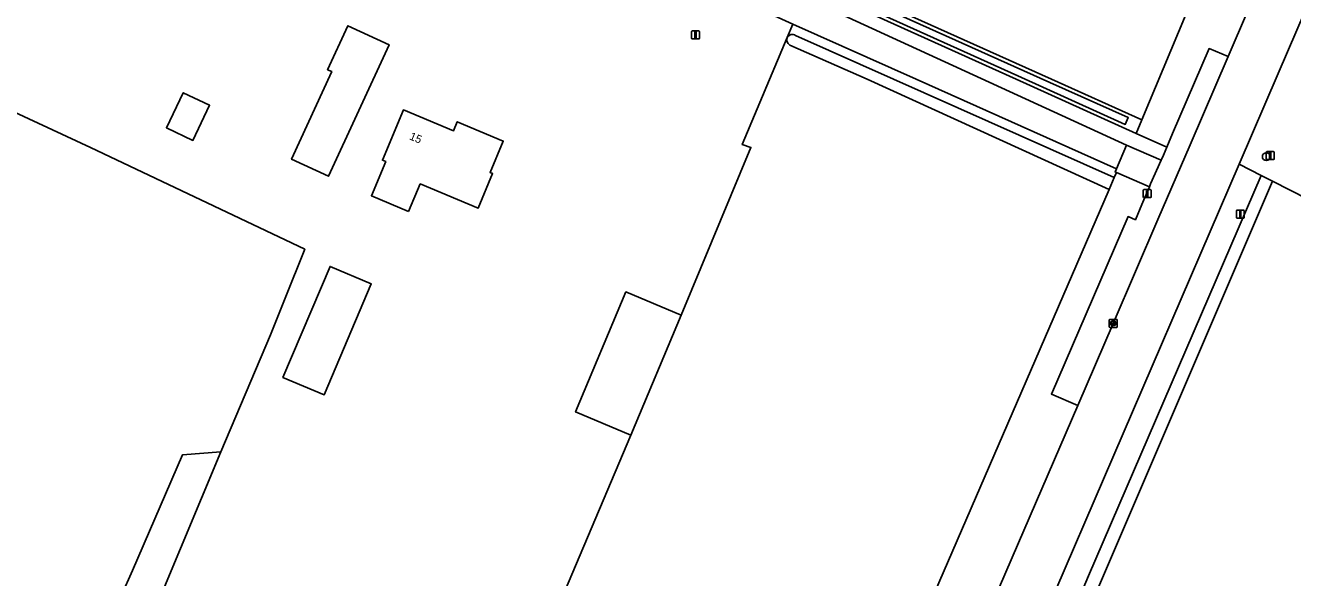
# Model space of a CAD drawing. Extents: x 155209 to 156748, y 385356 to 388487.
# Drawn here: x 155777.4 to 155935.8, y 385937.7 to 386006.7 of the extents above; entities that cross this region are included whole.
import ezdxf

# ---------------------------------------------------------------- set-up
doc = ezdxf.new("R2010")
doc.units = 0
for name, color, linetype in [('IMGEO_Berm_groen', 7, 'Continuous'), ('IMGEO_Boom', 7, 'Continuous'), ('IMGEO_Erf', 7, 'Continuous'), ('IMGEO_Gemengd_bos', 7, 'Continuous'), ('IMGEO_Grasland_agrarisch', 7, 'Continuous'), ('IMGEO_Groenvoorziening', 7, 'Continuous'), ('IMGEO_Kolk', 7, 'Continuous'), ('IMGEO_Lichtmast', 7, 'Continuous'), ('IMGEO_Loofbos', 7, 'Continuous'), ('IMGEO_Naaldbos', 7, 'Continuous'), ('IMGEO_Oever', 7, 'Continuous'), ('IMGEO_Pand', 7, 'Continuous'), ('IMGEO_Pand_nummerreeks', 7, 'Continuous'), ('IMGEO_Rijbaan_lokaal_gesloten', 7, 'Continuous'), ('IMGEO_Rijbaan_lokaal_open', 7, 'Continuous'), ('IMGEO_Voetpad_open', 7, 'Continuous'), ('IMGEO_Waterloop', 7, 'Continuous')]:
    doc.layers.add(name, color=color, linetype=linetype)

msp = doc.modelspace()

# ---------------------------------------------------------------- linework, layer by layer
at = {"layer": 'IMGEO_Berm_groen'}
for points in [[(156017.72, 386241.8), (155997.34, 386192.47), (155999.28, 386187.65), (155999.02, 386187.05), (155959.3, 386096.17), (155916.98, 385994.93), (155916.27, 385993.23), (155920.08, 385991.51), (155920.81, 385993.21), (155925.38, 386003.82), (155927.74, 386002.82), (155959.53, 386076.88), (155989.7, 386147.22), (156003.54, 386179.53)], [(155888.76, 386000), (155873.35, 386006.89), (155872.65, 386005.2)], [(155873.67, 386005.48), (155885.94, 386000), (155913.52, 385987.69), (155913.79, 385988.33), (155913.62, 385988.4), (155913.8, 385988.81), (155888.76, 386000)], [(155908.98, 385959.23), (155905.66, 385960.64), (155915.24, 385982.82), (155916.17, 385982.42), (155916.98, 385984.34), (155917.62, 385985.86), (155917.92, 385986.55), (155913.79, 385988.33), (155913.52, 385987.69), (155912.88, 385986.21), (155891.58, 385937.04), (155864.83, 385873.2), (155853.13, 385852.94), (155810.49, 385814.26), (155804.37, 385808.7), (155774.12, 385781.08), (155771.15, 385778.38), (155769.03, 385773.41), (155767.97, 385771.34), (155768.61, 385770.6), (155770.85, 385768.09), (155773.86, 385770.85), (155810.94, 385803.67), (155837.84, 385827.57)], [(155875.91, 385882.64), (155908.98, 385959.23)]]:
    msp.add_lwpolyline(points, dxfattribs=at)
msp.add_arc((155873.28, 386004.9), 0.7, 55.7075, 154.765, dxfattribs=at)
at = {"layer": 'IMGEO_Boom'}
msp.add_circle((155932.52, 385990.31), 0.489, dxfattribs=at)
at = {"layer": 'IMGEO_Erf'}
for points in [[(155853.12, 385955.51), (155846.2, 385958.41), (155852.48, 385973.4), (155859.4, 385970.5), (155868.12, 385991.46), (155867.03, 385991.83), (155872.65, 386005.2), (155873.35, 386006.89), (155838.02, 386023), (155837.33, 386022.91), (155786.93, 386045.9), (155786.05, 386043.98), (155767.96, 386004.93), (155765.9, 386000.59), (155785.57, 385991.44), (155812.34, 385978.74), (155809.88, 385972.63), (155808.05, 385968.03), (155801.87, 385953.41), (155776.85, 385893.52), (155754.19, 385839.25), (155761.09, 385835.71), (155796.45, 385820.47), (155833.54, 385909.24)], [(155815.33, 385987.87), (155810.71, 385989.99), (155815.73, 386000.94), (155815.21, 386001.18), (155817.73, 386006.67), (155822.88, 386004.31)], [(155795.06, 385993.93), (155797.16, 385998.31), (155800.45, 385996.74), (155798.36, 385992.35)], [(155825.33, 385983.48), (155820.67, 385985.43), (155822.46, 385989.7), (155822.05, 385989.87), (155824.68, 385996.15), (155830.93, 385993.53), (155831.4, 385994.67), (155837.15, 385992.26), (155835.51, 385988.34), (155835.83, 385988.2), (155834.01, 385983.87), (155826.78, 385986.91)], [(155809.62, 385962.73), (155815.51, 385976.59), (155820.66, 385974.4), (155814.77, 385960.54)]]:
    msp.add_lwpolyline(points, close=True, dxfattribs=at)
at = {"layer": 'IMGEO_Gemengd_bos'}
for points in [[(155872.65, 386005.2), (155867.03, 385991.83), (155868.12, 385991.46), (155859.4, 385970.5), (155853.12, 385955.51), (155833.54, 385909.24), (155796.45, 385820.47), (155810.49, 385814.26), (155853.13, 385852.94), (155864.83, 385873.2), (155891.58, 385937.04), (155912.88, 385986.21)], [(155912.88, 385986.21), (155882.62, 386000), (155872.98, 386004.27)]]:
    msp.add_lwpolyline(points, dxfattribs=at)
msp.add_arc((155873.34, 386004.92), 0.745, 157.9243, 241.0009, dxfattribs=at)
at = {"layer": 'IMGEO_Grasland_agrarisch'}
msp.add_lwpolyline([(155771.51, 385895.43), (155790.82, 385938.59), (155797.07, 385953.06), (155801.87, 385953.41), (155808.05, 385968.03), (155809.88, 385972.63), (155812.34, 385978.74), (155785.57, 385991.44), (155765.9, 386000.59)], dxfattribs=at)
at = {"layer": 'IMGEO_Groenvoorziening'}
for points in [[(155549.69, 386159.71), (155563.67, 386153.1), (155579.39, 386146.58), (155591.1, 386142.16), (155584.82, 386143.24), (155577.96, 386145.45), (155590.64, 386139.37), (155598.08, 386135.8), (155658.12, 386108.28), (155736.9, 386072.88), (155759.83, 386062.69), (155766.03, 386059.41), (155780.61, 386052.71), (155832.25, 386029.22), (155834.86, 386028.6), (155915.05, 385991.74), (155919.39, 385989.89), (155919.66, 385990.52), (155920.08, 385991.51), (155916.27, 385993.23), (155901.28, 386000), (155841.09, 386027.17), (155813.87, 386039.65)], [(155783.19, 385764.8), (155786.45, 385768.76), (155814.49, 385793.57), (155841.44, 385817.51), (155847.37, 385823.23), (155851.61, 385826.93), (155858.57, 385833.47), (155863.57, 385838.09), (155867.53, 385841.42), (155870.87, 385844.48), (155910.3, 385937.91), (155931.88, 385987.98), (155929.14, 385989.38), (155882.02, 385879.97)]]:
    msp.add_lwpolyline(points, dxfattribs=at)
at = {"layer": 'IMGEO_Kolk'}
for p, q in [((155912.89, 385969.05), (155912.89, 385969.9)), ((155912.97, 385969.98), (155913.82, 385969.98)), ((155913.82, 385968.98), (155912.97, 385968.98)), ((155913.15, 385969.47), (155913.15, 385969.48)), ((155913.59, 385969.43), (155913.19, 385969.43)), ((155913.2, 385969.52), (155913.59, 385969.52)), ((155913.38, 385969.76), (155913.41, 385969.76)), ((155913.4, 385969.2), (155913.38, 385969.2)), ((155913.64, 385969.48), (155913.64, 385969.47)), ((155913.89, 385969.9), (155913.89, 385969.05))]:
    msp.add_line(p, q, dxfattribs=at)
for points in [[(155912.89, 385969.05), (155912.89, 385969.9)], [(155912.97, 385969.98), (155913.82, 385969.98)], [(155913.82, 385968.98), (155912.97, 385968.98)], [(155913.89, 385969.9), (155913.89, 385969.05)]]:
    msp.add_lwpolyline(points, dxfattribs=at)
for centre, radius, start, end in [((155912.97, 385969.9), 0.0765, 91.552, 178.448), ((155912.97, 385969.9), 0.0765, 91.552, 178.448), ((155912.97, 385969.05), 0.0765, 181.552, 268.448), ((155912.97, 385969.05), 0.0765, 181.552, 268.448), ((155913.19, 385969.48), 0.0403, 85.8775, 175.7526), ((155913.19, 385969.47), 0.0366, 178.938, 274.7102), ((155913.6, 385969.48), 0.0386, 1.7309, 96.639), ((155913.59, 385969.48), 0.043, 264.8664, 352.4533), ((155913.82, 385969.9), 0.0765, 1.552, 88.448), ((155913.82, 385969.9), 0.0765, 1.552, 88.448), ((155913.82, 385969.05), 0.0765, 271.552, 358.448), ((155913.82, 385969.05), 0.0765, 271.552, 358.448)]:
    msp.add_arc(centre, radius, start, end, dxfattribs=at)
for centre, major_axis, ratio, start_param, end_param in [((155913.38, 385969.48), (-0.387, 0.002), 0.722429, 4.712389, 7.853982), ((155913.4, 385969.48), (-0.39, 0.002), 0.717154, 1.570796, 4.712389)]:
    msp.add_ellipse(centre, major_axis=major_axis, ratio=ratio, start_param=start_param, end_param=end_param, dxfattribs=at)
at = {"layer": 'IMGEO_Lichtmast'}
for p, q in [((155860.7, 386005.13), (155860.7, 386005.93)), ((155860.7, 386005.93), (155860.7, 386005.13)), ((155860.8, 386006.03), (155861.59, 386006.03)), ((155861.59, 386006.03), (155860.8, 386006.03)), ((155861.59, 386005.03), (155860.8, 386005.03)), ((155860.8, 386005.03), (155861.59, 386005.03)), ((155861.69, 386005.93), (155861.69, 386005.13)), ((155861.69, 386005.13), (155861.69, 386005.93)), ((155932.51, 385990.05), (155932.51, 385990.84)), ((155932.51, 385990.84), (155932.51, 385990.05)), ((155932.61, 385990.94), (155933.4, 385990.94)), ((155933.4, 385990.94), (155932.61, 385990.94)), ((155933.5, 385990.84), (155933.5, 385990.05)), ((155933.5, 385990.05), (155933.5, 385990.84)), ((155933.4, 385989.95), (155932.61, 385989.95)), ((155932.61, 385989.95), (155933.4, 385989.95)), ((155917.15, 385985.29), (155917.15, 385986.09)), ((155917.15, 385986.09), (155917.15, 385985.29)), ((155917.25, 385986.19), (155918.04, 385986.19)), ((155918.04, 385986.19), (155917.25, 385986.19)), ((155918.14, 385986.09), (155918.14, 385985.29)), ((155918.14, 385985.29), (155918.14, 385986.09)), ((155918.04, 385985.19), (155917.25, 385985.19)), ((155917.25, 385985.19), (155918.04, 385985.19)), ((155928.78, 385982.74), (155928.78, 385983.53)), ((155928.78, 385983.53), (155928.78, 385982.74)), ((155928.88, 385983.63), (155929.67, 385983.63)), ((155929.67, 385983.63), (155928.88, 385983.63)), ((155929.77, 385983.53), (155929.77, 385982.74)), ((155929.77, 385982.74), (155929.77, 385983.53)), ((155929.67, 385982.64), (155928.88, 385982.64)), ((155928.88, 385982.64), (155929.67, 385982.64))]:
    msp.add_line(p, q, dxfattribs=at)
for points in [[(155861.12, 386005.9), (155861.27, 386005.9), (155861.27, 386005.15), (155861.12, 386005.15), (155861.12, 386005.9)], [(155932.93, 385990.82), (155933.08, 385990.82), (155933.08, 385990.07), (155932.93, 385990.07), (155932.93, 385990.82)], [(155917.57, 385986.06), (155917.72, 385986.06), (155917.72, 385985.31), (155917.57, 385985.31), (155917.57, 385986.06)], [(155929.2, 385983.51), (155929.35, 385983.51), (155929.35, 385982.76), (155929.2, 385982.76), (155929.2, 385983.51)]]:
    msp.add_lwpolyline(points, dxfattribs=at)
for centre, start, end in [((155860.8, 386005.93), 90, 180), ((155860.8, 386005.93), 90, 180), ((155860.8, 386005.13), 180, 270), ((155860.8, 386005.13), 180, 270), ((155861.59, 386005.93), 0, 90), ((155861.59, 386005.93), 360, 90), ((155861.59, 386005.13), 270, 0), ((155861.59, 386005.13), 270, 0), ((155932.61, 385990.84), 90, 180), ((155932.61, 385990.84), 90, 180), ((155933.4, 385990.84), 0, 90), ((155933.4, 385990.84), 360, 90), ((155932.61, 385990.05), 180, 270), ((155932.61, 385990.05), 180, 270), ((155933.4, 385990.05), 270, 0), ((155933.4, 385990.05), 270, 0), ((155917.25, 385986.09), 90, 180), ((155917.25, 385986.09), 90, 180), ((155918.04, 385986.09), 0, 90), ((155918.04, 385986.09), 360, 90), ((155917.25, 385985.29), 180, 270), ((155917.25, 385985.29), 180, 270), ((155918.04, 385985.29), 270, 0), ((155918.04, 385985.29), 270, 0), ((155928.88, 385983.53), 90, 180), ((155928.88, 385983.53), 90, 180), ((155929.67, 385983.53), 0, 90), ((155929.67, 385983.53), 360, 90), ((155928.88, 385982.74), 180, 270), ((155928.88, 385982.74), 180, 270), ((155929.67, 385982.74), 270, 0), ((155929.67, 385982.74), 270, 0)]:
    msp.add_arc(centre, 0.1, start, end, dxfattribs=at)
at = {"layer": 'IMGEO_Loofbos'}
msp.add_lwpolyline([(155886.19, 386008.74), (155905.67, 386000), (155916.98, 385994.93), (155959.3, 386096.17), (155999.02, 386187.05)], dxfattribs=at)
msp.add_lwpolyline([(155776.85, 385893.52), (155801.87, 385953.41), (155797.07, 385953.06), (155790.82, 385938.59), (155771.51, 385895.43)], close=True, dxfattribs=at)
at = {"layer": 'IMGEO_Naaldbos'}
msp.add_lwpolyline([(155974.75, 385944.88), (155969.49, 385947.2), (155967.94, 385952.96), (155961.9, 385955.8), (155959.69, 385962.26), (155956.09, 385964.8), (155955.77, 385969.98), (155948.24, 385973.41), (155946.55, 385980.5), (155933.29, 385987.26), (155871.9, 385843.96), (155870.19, 385841.27), (155853.47, 385801.77), (155851.64, 385797.46), (155932.5, 385882.64)], close=True, dxfattribs=at)
at = {"layer": 'IMGEO_Oever'}
for points in [[(155885.99, 386008.33), (155905.49, 385999.59), (155915.28, 385995.19), (155914.9, 385994.35), (155901.47, 386000.41), (155841.28, 386027.59), (155814.1, 386040.05)], [(155813.87, 386039.65), (155841.09, 386027.17), (155901.28, 386000), (155916.27, 385993.23)], [(155916.27, 385993.23), (155916.98, 385994.93), (155905.67, 386000), (155886.19, 386008.74)]]:
    msp.add_lwpolyline(points, dxfattribs=at)
at = {"layer": 'IMGEO_Pand'}
for points in [[(155822.88, 386004.31), (155817.73, 386006.67), (155815.21, 386001.18), (155815.73, 386000.94), (155810.71, 385989.99), (155815.33, 385987.87)], [(155797.16, 385998.31), (155795.06, 385993.93), (155798.36, 385992.35), (155800.45, 385996.74)], [(155825.33, 385983.48), (155826.78, 385986.91), (155834.01, 385983.87), (155835.83, 385988.2), (155835.51, 385988.34), (155837.15, 385992.26), (155831.4, 385994.67), (155830.93, 385993.53), (155824.68, 385996.15), (155822.05, 385989.87), (155822.46, 385989.7), (155820.67, 385985.43)], [(155814.77, 385960.54), (155820.66, 385974.4), (155815.51, 385976.59), (155809.62, 385962.73)], [(155859.4, 385970.5), (155852.48, 385973.4), (155846.2, 385958.41), (155853.12, 385955.51)]]:
    msp.add_lwpolyline(points, close=True, dxfattribs=at)
at = {"layer": 'IMGEO_Rijbaan_lokaal_gesloten'}
for points in [[(155944.24, 386024.53), (155949.14, 386035.92), (155965.64, 386074.34), (155984.91, 386119.23), (156009.58, 386176.82), (156003.54, 386179.53), (155989.7, 386147.22), (155959.53, 386076.88), (155927.74, 386002.82), (155923, 385991.79), (155918.96, 385982.46), (155913.39, 385969.48), (155908.98, 385959.23), (155875.91, 385882.64)], [(155882.02, 385879.97), (155929.14, 385989.38), (155934.02, 386000.73), (155944.24, 386024.53)]]:
    msp.add_lwpolyline(points, dxfattribs=at)
at = {"layer": 'IMGEO_Rijbaan_lokaal_open'}
msp.add_lwpolyline([(155780.61, 386052.71), (155766.03, 386059.41), (155759.83, 386062.69), (155736.9, 386072.88), (155735.52, 386070.28), (155735.2, 386069.65), (155735.55, 386069.49), (155763.02, 386056.8), (155774.57, 386051.53), (155786.93, 386045.9), (155837.33, 386022.91), (155838.02, 386023), (155873.35, 386006.89), (155888.76, 386000), (155913.8, 385988.81), (155915.05, 385991.74), (155834.86, 386028.6), (155832.25, 386029.22)], close=True, dxfattribs=at)
at = {"layer": 'IMGEO_Voetpad_open'}
msp.add_lwpolyline([(155944.24, 386024.53), (155934.02, 386000.73), (155929.14, 385989.38), (155931.88, 385987.98), (155933.29, 385987.26), (155946.55, 385980.5)], dxfattribs=at)
for points in [[(155927.74, 386002.82), (155925.38, 386003.82), (155920.81, 385993.21), (155920.08, 385991.51), (155919.66, 385990.52), (155919.39, 385989.89), (155918.07, 385986.9), (155917.92, 385986.55), (155917.62, 385985.86), (155916.98, 385984.34), (155916.17, 385982.42), (155915.24, 385982.82), (155905.66, 385960.64), (155908.98, 385959.23), (155913.39, 385969.48), (155918.96, 385982.46), (155923, 385991.79)], [(155919.39, 385989.89), (155915.05, 385991.74), (155913.8, 385988.81), (155913.62, 385988.4), (155913.79, 385988.33), (155917.92, 385986.55), (155918.07, 385986.9)]]:
    msp.add_lwpolyline(points, close=True, dxfattribs=at)
at = {"layer": 'IMGEO_Waterloop'}
for points in [[(155814.1, 386040.05), (155841.28, 386027.59), (155901.47, 386000.41), (155914.9, 385994.35), (155915.28, 385995.19), (155905.49, 385999.59), (155885.99, 386008.33)], [(155885.94, 386000), (155873.67, 386005.48)], [(155872.98, 386004.27), (155882.62, 386000), (155912.88, 385986.21), (155913.52, 385987.69), (155885.94, 386000)], [(155933.29, 385987.26), (155931.88, 385987.98), (155910.3, 385937.91), (155870.87, 385844.48)], [(155871.9, 385843.96), (155933.29, 385987.26)]]:
    msp.add_lwpolyline(points, dxfattribs=at)
for centre, radius, start, end in [((155873.34, 386004.92), 0.745, 157.9243, 241.0009), ((155873.28, 386004.9), 0.7, 55.7075, 154.765)]:
    msp.add_arc(centre, radius, start, end, dxfattribs=at)

# ---------------------------------------------------------------- texts
at = {"layer": 'IMGEO_Pand_nummerreeks'}
msp.add_text('15', height=1, rotation=337.312, dxfattribs=at).set_placement((155825.35, 385992.5))

doc.saveas('drawing.dxf')
